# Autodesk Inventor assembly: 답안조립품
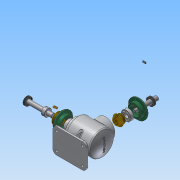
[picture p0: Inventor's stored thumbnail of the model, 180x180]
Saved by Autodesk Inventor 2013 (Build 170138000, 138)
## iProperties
Created: 2016-09
Part Number: 답안조립품
Document SubType Name: Assembly
Designer: Administrator
Author: Administrator
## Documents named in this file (14)
- C:\Users\Administrator\Desktop\460908V1012\답안조립품.iam
- C:\Users\Administrator\Desktop\460908V1012\M4.ipt
- C:\Users\Administrator\Desktop\460908V1012\메인 베벨기어.ipt
- C:\Users\Administrator\Desktop\460908V1012\메인 축.ipt
- 메인 축.ipt
- C:\Users\Administrator\Desktop\460908V1012\베어링 6203.ipt
- C:\Users\Administrator\Desktop\460908V1012\본체.ipt
- C:\Users\Administrator\Desktop\460908V1012\서브 베벨기어.ipt
- C:\Users\Administrator\Desktop\460908V1012\서브 축.ipt
- 서브 축.ipt
- C:\Users\Administrator\Desktop\460908V1012\오일실 17 32 8.ipt
- C:\Users\Administrator\Desktop\460908V1012\커버.ipt
- C:\Users\Administrator\Desktop\460908V1012\키 4x4.ipt
- C:\Users\Administrator\Desktop\460908V1012\키 5x5.ipt
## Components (1 placed, 1 different names)
1. M4:1
